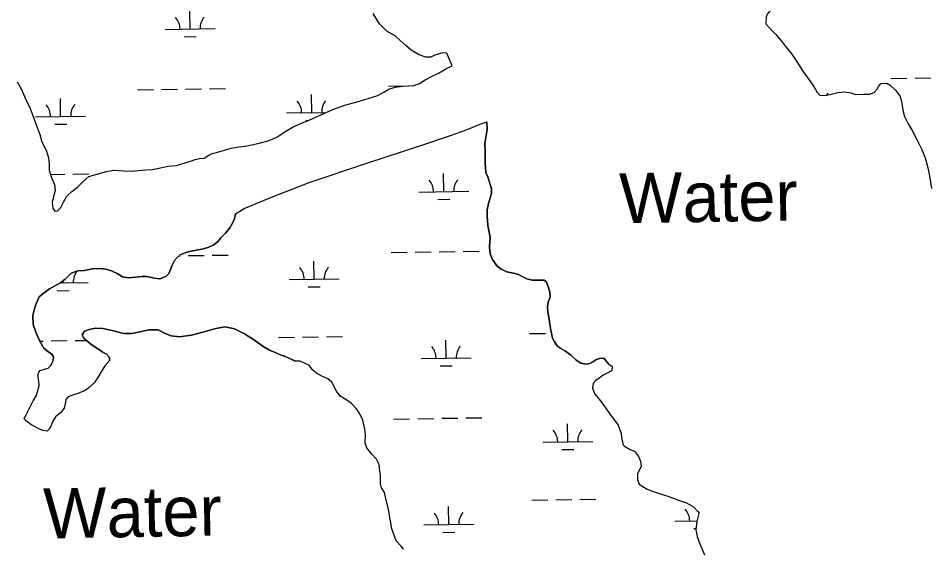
# Model space of a CAD drawing. Extents: x 3812694 to 3850888, y 319753 to 345638.
# Drawn here: x 3820130 to 3821954, y 335763 to 336823 of the extents above; entities that cross this region are included whole.
import ezdxf

# ---------------------------------------------------------------- set-up
doc = ezdxf.new("R2010")
doc.units = 0
for name, color, linetype in [('V-RIVR-IDEN', 7, 'Continuous'), ('V-TOPO-SHOR', 7, 'Continuous'), ('V-WETL-SWMP', 7, 'Continuous')]:
    doc.layers.add(name, color=color, linetype=linetype)

msp = doc.modelspace()

# ---------------------------------------------------------------- linework, layer by layer
at = {"layer": 'V-TOPO-SHOR'}
for points in [[(3822718.6, 337347.9), (3822729.1, 337350), (3822736.4, 337343), (3822761.6, 337270.6), (3822762.6, 337261.9), (3822761.8, 337259.2), (3822742.8, 337248.3), (3822605, 337198.7), (3822369.6, 337114.4), (3822324.5, 337103.7), (3822232.9, 337064.8), (3822065.7, 337003), (3821927.6, 336950.4), (3821828.7, 336915.3), (3821709.1, 336870.2), (3821667.3, 336856.5), (3821652.4, 336851.4), (3821643.1, 336846.5), (3821634.5, 336839.5), (3821630.6, 336835.4), (3821627.1, 336830.7), (3821625, 336824.9), (3821624.3, 336811.5)], [(3820997.4, 336727.2), (3820989.7, 336744.7), (3820986.6, 336752.6), (3820978.8, 336753.5), (3820962.2, 336748.6), (3820954.4, 336744.6), (3820944.8, 336745.1), (3820931.5, 336749.8), (3820915.5, 336758.7), (3820904.6, 336768.4), (3820892.3, 336779), (3820883.6, 336786.5), (3820866.8, 336796.7), (3820858.6, 336804.6), (3820851.7, 336811.5), (3820839.4, 336832.2)], [(3821624.3, 336811.5), (3821635.6, 336798.7), (3821644, 336789.8), (3821655.2, 336776.5), (3821663.8, 336766.2), (3821674.1, 336753.6), (3821683.1, 336740.9), (3821690.4, 336729.2), (3821698.5, 336716.6), (3821710.4, 336700.1), (3821719.9, 336686.3), (3821726.6, 336674.5)], [(3820501.6, 336542.9), (3820510.8, 336549.2), (3820517.5, 336552.1), (3820528.1, 336555.2), (3820541.9, 336559.3), (3820555.5, 336562.7), (3820571.1, 336565.5), (3820587.3, 336568), (3820599.4, 336570.2), (3820613.8, 336573.7), (3820629.4, 336578), (3820646.9, 336584.9), (3820664.7, 336597.1), (3820679.1, 336605.8), (3820696.1, 336613.3), (3820717.1, 336621.8), (3820740.9, 336632.3), (3820762, 336641.8), (3820784.5, 336649.8), (3820807.5, 336655.3), (3820846.4, 336667.3), (3820860.4, 336674.7), (3820870.6, 336680.6), (3820883.3, 336684.6), (3820897.9, 336686.7), (3820910.9, 336687.8), (3820920.3, 336688.4), (3820931.7, 336692.3), (3820943.5, 336699.5), (3820955.8, 336705.9), (3820970, 336713), (3820985.8, 336722), (3820997.4, 336727.2)], [(3820127.6, 336695.8), (3820136.5, 336680), (3820144, 336661.4), (3820153.4, 336642.1), (3820161.8, 336621), (3820167.2, 336606.2), (3820172.7, 336590.4), (3820176.5, 336577.4), (3820186, 336556.7), (3820190.4, 336543.5), (3820191.7, 336531.9), (3820191.6, 336518.2), (3820197, 336502.3), (3820202, 336490.7), (3820203.8, 336478.4), (3820200.9, 336468.8), (3820197.8, 336455.1), (3820199.1, 336443.2), (3820202.8, 336437.1), (3820208.5, 336437.8), (3820214.6, 336444.6), (3820219.9, 336454.8), (3820227, 336466.9), (3820236.9, 336476.5), (3820248.1, 336485.2), (3820259.2, 336496.1), (3820270.7, 336506.4), (3820284.6, 336510.7), (3820306, 336516.6), (3820320.9, 336518.9), (3820340.4, 336517.6), (3820358.1, 336516.8), (3820369.1, 336518.2), (3820384.6, 336519.5)], [(3821726.6, 336674.5), (3821732, 336669.1), (3821743.2, 336668.5), (3821755.1, 336671.2), (3821768, 336674), (3821781.7, 336675.6), (3821794.1, 336673.3), (3821803.7, 336670.5), (3821819.2, 336670.7), (3821832.4, 336670.7), (3821841.1, 336674), (3821846.8, 336680.8), (3821849.9, 336686.9), (3821854.3, 336692), (3821866, 336692.6), (3821872.7, 336688.8), (3821883.3, 336678.8), (3821892.4, 336667.3), (3821895.7, 336656.9), (3821897.8, 336639.1), (3821901.4, 336626.3), (3821908.7, 336611.7), (3821916.9, 336598), (3821926.3, 336580.5), (3821935.3, 336561.5), (3821942.5, 336543.7), (3821946.7, 336529.3), (3821950.1, 336514.5), (3821952.7, 336499.3), (3821955.3, 336482.4)], [(3820563.7, 336431.7), (3820573, 336437.3), (3820581.5, 336442.4), (3820593, 336447.4), (3820635.7, 336465.2), (3820711.2, 336494.6), (3820828.3, 336533.6), (3820936.5, 336569.2), (3820993.8, 336588.1), (3821016.8, 336596.3), (3821037.3, 336604.2), (3821047.9, 336608.9), (3821066.2, 336615.6)], [(3821309.4, 336132), (3821301.2, 336142.5), (3821299.3, 336143.4), (3821292, 336143), (3821288.8, 336142.1), (3821284.6, 336139.9), (3821278.6, 336135.8), (3821272.6, 336132.6), (3821264.8, 336131.3), (3821254.7, 336133.3), (3821244.2, 336140.2), (3821234.2, 336149.5), (3821223.8, 336157.4), (3821213.3, 336163.4), (3821206.4, 336169), (3821201, 336177.7), (3821197.8, 336183.7), (3821194.7, 336199.4), (3821192.6, 336211.3), (3821190.8, 336221.4), (3821188.6, 336235.7), (3821187.8, 336246.7), (3821189.3, 336255.4), (3821193, 336265.4), (3821192.6, 336275.5), (3821189.1, 336286.6), (3821185.5, 336295.3), (3821180.9, 336299), (3821167.6, 336299.6), (3821157.1, 336299.2), (3821146.5, 336302.1), (3821138.3, 336305.8), (3821130.1, 336310.5), (3821119.6, 336313.3), (3821106.3, 336315.7), (3821094.9, 336321.3), (3821086.7, 336327.8), (3821078, 336340.3), (3821073.1, 336351.8), (3821071.8, 336365.6), (3821072.9, 336385.3), (3821068.5, 336408.7), (3821066.9, 336428), (3821067, 336439.9), (3821069.8, 336452.3), (3821073.6, 336465.6), (3821076, 336473.8), (3821076, 336479.3), (3821076, 336481.6), (3821068.4, 336506), (3821064.8, 336514.3), (3821063.6, 336525.3), (3821063.2, 336533.5), (3821063.3, 336543.6), (3821062.9, 336556.9), (3821062.6, 336571.6), (3821064, 336580.3), (3821067.4, 336600), (3821066.2, 336615.6)], [(3820384.6, 336519.5), (3820398.4, 336520.7), (3820429.1, 336527.2), (3820445.9, 336528.7), (3820463.3, 336533.6), (3820469.3, 336536), (3820477.9, 336538.5), (3820483.5, 336540.3), (3820492.1, 336542.1), (3820501.6, 336542.9)], [(3820563.7, 336431.7), (3820561.7, 336421.8), (3820558.3, 336413), (3820552.7, 336404.1), (3820543.8, 336393.3), (3820535.2, 336384.4), (3820528.7, 336376.6), (3820521, 336369.7), (3820509.4, 336364.7), (3820496.4, 336361.3), (3820485.5, 336359.1), (3820474.8, 336357.3), (3820463.3, 336353.8), (3820453.5, 336349.7), (3820447.2, 336344.5), (3820442, 336338.8), (3820437.2, 336329.5), (3820433.8, 336320.8), (3820430.6, 336312.6), (3820424.6, 336306.3), (3820412.7, 336302.2), (3820401.4, 336303.1), (3820387.7, 336306.4), (3820376.6, 336306.8), (3820364.5, 336305.5), (3820349.9, 336304), (3820338.3, 336306.1), (3820327.2, 336312.9), (3820316.2, 336318.2), (3820307.6, 336320.7), (3820295.8, 336322.8), (3820277.5, 336321.7), (3820262.4, 336318.5), (3820248.6, 336318), (3820235.8, 336313.4), (3820229.5, 336307.5), (3820223.2, 336301.6), (3820214, 336293.7), (3820205.5, 336289.5), (3820192.3, 336282.1), (3820181.3, 336274.1), (3820171.6, 336265.8), (3820163.8, 336247.1), (3820158.6, 336228.6), (3820159.4, 336210.4), (3820164.8, 336195.7), (3820170.9, 336181.2), (3820178.9, 336166.7), (3820180.1, 336164.2), (3820188.9, 336156.9), (3820196.1, 336152.1), (3820200.2, 336146.4), (3820199.6, 336139.6)], [(3820312.5, 336139.2), (3820311.7, 336145.4), (3820306, 336151.1), (3820297.2, 336156.4), (3820294.4, 336158.8), (3820285.6, 336164.4), (3820274.6, 336171.3), (3820260.9, 336183.3), (3820257.6, 336190.1), (3820262, 336197.4), (3820271.5, 336201), (3820283.5, 336203.1), (3820299.1, 336202.6), (3820317.8, 336198.5), (3820341, 336192.8), (3820357.2, 336192.6), (3820376, 336196.5), (3820391.6, 336200), (3820409.1, 336199.9), (3820423.1, 336193), (3820435.6, 336188.3), (3820451.9, 336186), (3820476.1, 336189.2), (3820498.5, 336195.4), (3820524.6, 336202.6), (3820543.1, 336206.1), (3820562.3, 336202.2), (3820582.2, 336192.3), (3820601.7, 336179.5), (3820619.6, 336166.5), (3820631.8, 336159.7), (3820643.4, 336154.7), (3820655.3, 336149.7), (3820662.1, 336147.5), (3820663.6, 336146.5), (3820684.1, 336137.4)], [(3820312.5, 336139.2), (3820302.9, 336128.3), (3820295.4, 336116), (3820288.5, 336105.1), (3820281.6, 336094.2), (3820270.6, 336083.9), (3820263.8, 336078.5), (3820248.7, 336073.1), (3820238.4, 336069.7), (3820229.5, 336066.3), (3820224.7, 336060.8), (3820224, 336055.3), (3820221.2, 336043.7), (3820214.4, 336034.2), (3820204.1, 336026), (3820198.6, 336017.8), (3820193.1, 336002.7), (3820187.6, 335997.3), (3820178.7, 335998.7), (3820169.8, 336002.8), (3820154.8, 336011.1), (3820145.9, 336017.3), (3820141.8, 336022.7), (3820144.5, 336027.5), (3820159.7, 336058.3), (3820165.9, 336069.2), (3820168, 336076), (3820171.4, 336089), (3820170.8, 336097.2), (3820168.7, 336108.9), (3820170.8, 336115.7), (3820173.6, 336119.1), (3820182.5, 336121.2), (3820189.3, 336123.2), (3820194.8, 336128.6), (3820196.9, 336132.1), (3820199.6, 336139.6)], [(3820899.8, 335761.8), (3820895, 335767.9), (3820885.5, 335778.2), (3820876.7, 335802.2), (3820869.9, 335841.2), (3820864.5, 335863.1), (3820861.8, 335874.8), (3820855.7, 335884.4), (3820853.7, 335892.6), (3820853.7, 335909.7), (3820852.4, 335917.2), (3820851.1, 335930.9), (3820845.6, 335941.9), (3820836.1, 335952.2), (3820826.5, 335964.5), (3820823.1, 335974.1), (3820823.9, 335990.5), (3820822.5, 336001.5), (3820818.5, 336019.3), (3820812.4, 336032.3), (3820806.2, 336041.9), (3820796, 336052.9), (3820784.4, 336061.1), (3820773.5, 336067.3), (3820766, 336077.6), (3820756.5, 336095.4), (3820748.3, 336102.3), (3820738, 336107.1), (3820726.4, 336112.6), (3820717.5, 336120.9), (3820712.1, 336129.1), (3820693.6, 336137.4), (3820684.1, 336137.4)], [(3821309.4, 336132), (3821316.9, 336126.6), (3821316.9, 336124.5), (3821315.5, 336118.3), (3821307.3, 336113.6), (3821299.1, 336109.5), (3821290.9, 336103.4), (3821284.7, 336098.6), (3821279.2, 336092.5), (3821277.8, 336083.6), (3821282.6, 336071.2), (3821293.5, 336058.2), (3821311.9, 336032.8), (3821328.9, 336009.5), (3821335, 335993.1), (3821336.3, 335981.4), (3821339, 335970.5), (3821341.8, 335967.7), (3821352.7, 335960.9), (3821361.6, 335957.4), (3821369.8, 335947.1), (3821373.8, 335937.5), (3821375.2, 335927.9), (3821373.1, 335923.2), (3821367.6, 335912.9), (3821367.6, 335901.3), (3821371, 335891.7), (3821387.3, 335881.4), (3821405.1, 335875.2), (3821430.4, 335866.9), (3821449.5, 335860), (3821465.3, 335854.5), (3821479.6, 335846.2), (3821488.5, 335837.3), (3821491.2, 335833.9), (3821490.5, 335833.2), (3821486.4, 335816.8), (3821484.3, 335800.3), (3821487, 335787.3), (3821492.4, 335772.3), (3821501.9, 335750.3)]]:
    msp.add_lwpolyline(points, dxfattribs=at)
at = {"layer": 'V-WETL-SWMP'}
for p, q in [((3820473.3, 336801.2), (3820472.7, 336837.2)), ((3820423.3, 336800.4), (3820523.3, 336801.9)), ((3820461.5, 336785.6), (3820485.5, 336785.9)), ((3820870.1, 336687.1), (3820902.1, 336687.6)), ((3821873.8, 336702.3), (3821905.8, 336702.8)), ((3821921.8, 336703), (3821953.8, 336703.5)), ((3820368.3, 336679.5), (3820400.3, 336680)), ((3820416.3, 336680.2), (3820448.3, 336680.7)), ((3820464.2, 336680.9), (3820496.2, 336681.4)), ((3820512.2, 336681.7), (3820544.2, 336682.2)), ((3820716.3, 336634), (3820715.8, 336670)), ((3820214.5, 336626.4), (3820213.9, 336662.4)), ((3820666.3, 336633.3), (3820745.6, 336634.5)), ((3820164.5, 336625.7), (3820264.4, 336627.2)), ((3820704.5, 336618.4), (3820708.8, 336618.5)), ((3820202.7, 336610.8), (3820226.7, 336611.2)), ((3820194.1, 336510.7), (3820222.8, 336511.1)), ((3820238.8, 336511.3), (3820270.8, 336511.8)), ((3820980.2, 336476.1), (3820979.6, 336512.1)), ((3820930.2, 336475.4), (3821030.2, 336476.9)), ((3820968.4, 336460.5), (3820992.4, 336460.9)), ((3820451.6, 336348), (3820453.3, 336348.1)), ((3820469.3, 336348.3), (3820501.3, 336348.8)), ((3820517.3, 336349), (3820549.3, 336349.5)), ((3820875.1, 336354.4), (3820907.1, 336354.9)), ((3820923.1, 336355.2), (3820955.1, 336355.7)), ((3820971.1, 336355.9), (3821003.1, 336356.4)), ((3821019.1, 336356.6), (3821051.1, 336357.1)), ((3820721.3, 336301.4), (3820720.8, 336337.4)), ((3820213.9, 336293.7), (3820269.5, 336294.5)), ((3820219.5, 336293.8), (3820219.4, 336298.4)), ((3820671.3, 336300.6), (3820771.3, 336302.1)), ((3820709.6, 336285.8), (3820733.6, 336286.1)), ((3820207.7, 336278.2), (3820231.7, 336278.5)), ((3820172.8, 336177.6), (3820179.8, 336177.7)), ((3820195.8, 336178), (3820227.8, 336178.5)), ((3820243.8, 336178.7), (3820265.8, 336179)), ((3820649.7, 336184.8), (3820681.7, 336185.3)), ((3820697.7, 336185.6), (3820729.7, 336186.1)), ((3820745.7, 336186.3), (3820777.7, 336186.8)), ((3820985.2, 336143.5), (3820984.6, 336179.5)), ((3821151.5, 336192.4), (3821183.5, 336192.9)), ((3820935.2, 336142.7), (3821035.2, 336144.2)), ((3820973.4, 336127.9), (3820997.4, 336128.2)), ((3820880.2, 336021.8), (3820912.2, 336022.3)), ((3820928.2, 336022.5), (3820960.2, 336023)), ((3820976.2, 336023.3), (3821008.2, 336023.7)), ((3821024.2, 336024), (3821056.2, 336024.5)), ((3821228.2, 335976.3), (3821227.7, 336012.3)), ((3821178.2, 335975.6), (3821278.2, 335977.1)), ((3821216.5, 335960.7), (3821240.5, 335961.1)), ((3821156.6, 335859.8), (3821188.6, 335860.3)), ((3821204.6, 335860.5), (3821236.6, 335861)), ((3821252.6, 335861.2), (3821284.6, 335861.7)), ((3820990.2, 335810.8), (3820989.7, 335846.8)), ((3821442.1, 335817.7), (3821486.8, 335818.4)), ((3820940.2, 335810.1), (3821040.2, 335811.6)), ((3820978.5, 335795.2), (3821002.5, 335795.6)), ((3821480.3, 335802.8), (3821484.6, 335802.9))]:
    msp.add_line(p, q, dxfattribs=at)
for points in [[(3820127.6, 336695.8), (3820136.5, 336680), (3820144, 336661.4), (3820153.4, 336642.1), (3820161.8, 336621), (3820167.2, 336606.2), (3820172.7, 336590.4), (3820176.5, 336577.4), (3820186, 336556.7), (3820190.4, 336543.5), (3820191.7, 336531.9), (3820191.6, 336518.2), (3820197, 336502.3), (3820202, 336490.7), (3820203.8, 336478.4), (3820200.9, 336468.8), (3820197.8, 336455.1), (3820199.1, 336443.2), (3820202.8, 336437.1), (3820208.5, 336437.8), (3820214.6, 336444.6), (3820219.9, 336454.8), (3820227, 336466.9), (3820236.9, 336476.5), (3820248.1, 336485.2), (3820259.2, 336496.1), (3820270.7, 336506.4), (3820284.6, 336510.7), (3820306, 336516.6), (3820320.9, 336518.9), (3820340.4, 336517.6), (3820358.1, 336516.8), (3820369.1, 336518.2), (3820384.6, 336519.5), (3820398.4, 336520.7), (3820429.1, 336527.2), (3820445.9, 336528.7), (3820463.3, 336533.6), (3820469.3, 336536), (3820477.9, 336538.5), (3820483.5, 336540.3), (3820492.1, 336542.1), (3820501.6, 336542.9), (3820510.8, 336549.2), (3820517.5, 336552.1), (3820528.1, 336555.2), (3820541.9, 336559.3), (3820555.5, 336562.7), (3820571.1, 336565.5), (3820587.3, 336568), (3820599.4, 336570.2), (3820613.8, 336573.7), (3820629.4, 336578), (3820646.9, 336584.9), (3820664.7, 336597.1), (3820679.1, 336605.8), (3820696.1, 336613.3), (3820717.1, 336621.8), (3820740.9, 336632.3), (3820762, 336641.8), (3820784.5, 336649.8), (3820807.5, 336655.3), (3820846.4, 336667.3), (3820860.4, 336674.7), (3820870.6, 336680.6), (3820883.3, 336684.6), (3820897.9, 336686.7), (3820910.9, 336687.8), (3820920.3, 336688.4), (3820931.7, 336692.3), (3820943.5, 336699.5), (3820955.8, 336705.9), (3820970, 336713), (3820985.8, 336722), (3820997.4, 336727.2), (3820989.7, 336744.7), (3820986.6, 336752.6), (3820978.8, 336753.5), (3820962.2, 336748.6), (3820954.4, 336744.6), (3820944.8, 336745.1), (3820931.5, 336749.8), (3820915.5, 336758.7), (3820904.6, 336768.4), (3820892.3, 336779), (3820883.6, 336786.5), (3820866.8, 336796.7), (3820858.6, 336804.6), (3820851.7, 336811.5), (3820839.4, 336832.2)], [(3821625, 336824.9), (3821624.3, 336811.5), (3821635.6, 336798.7), (3821644, 336789.8), (3821655.2, 336776.5), (3821663.8, 336766.2), (3821674.1, 336753.6), (3821683.1, 336740.9), (3821690.4, 336729.2), (3821698.5, 336716.6), (3821710.4, 336700.1), (3821719.9, 336686.3), (3821726.6, 336674.5), (3821732, 336669.1), (3821743.2, 336668.5), (3821755.1, 336671.2), (3821768, 336674), (3821781.7, 336675.6), (3821794.1, 336673.3), (3821803.7, 336670.5), (3821819.3, 336670.7), (3821832.4, 336670.7), (3821841.1, 336674), (3821846.8, 336680.8), (3821849.9, 336686.9), (3821854.3, 336692), (3821866, 336692.6), (3821872.7, 336688.8), (3821883.3, 336678.8), (3821892.4, 336667.3), (3821895.7, 336656.9), (3821897.8, 336639.1), (3821901.4, 336626.3), (3821908.7, 336611.7), (3821916.9, 336598), (3821926.3, 336580.5), (3821935.3, 336561.5), (3821942.5, 336543.7), (3821946.7, 336529.3), (3821950.1, 336514.5), (3821952.7, 336499.3), (3821955.3, 336482.4)], [(3820376.6, 336306.8), (3820387.7, 336306.4), (3820401.4, 336303.1), (3820412.7, 336302.2), (3820424.6, 336306.3), (3820430.6, 336312.6), (3820433.8, 336320.8), (3820437.2, 336329.5), (3820442, 336338.8), (3820447.2, 336344.5), (3820453.5, 336349.7), (3820463.3, 336353.8), (3820474.8, 336357.3), (3820485.5, 336359.1), (3820496.4, 336361.3), (3820509.4, 336364.7), (3820521, 336369.7), (3820528.7, 336376.6), (3820535.2, 336384.4), (3820543.8, 336393.3), (3820552.7, 336404.1), (3820558.3, 336413), (3820561.7, 336421.8), (3820563.7, 336431.7), (3820573, 336437.3), (3820581.5, 336442.4), (3820593, 336447.4), (3820635.7, 336465.2), (3820711.2, 336494.6), (3820828.3, 336533.6), (3820936.5, 336569.2), (3820993.8, 336588.1), (3821016.8, 336596.3), (3821037.3, 336604.2), (3821047.9, 336608.9), (3821066.2, 336615.6), (3821067.4, 336600), (3821064, 336580.3), (3821062.6, 336571.6), (3821062.9, 336556.9), (3821063.3, 336543.6), (3821063.2, 336533.5), (3821063.6, 336525.3), (3821064.8, 336514.3), (3821068.4, 336506), (3821076, 336481.6), (3821076, 336479.3), (3821076, 336473.8), (3821073.6, 336465.6), (3821069.8, 336452.3), (3821067, 336439.9), (3821066.9, 336428), (3821068.5, 336408.7), (3821072.9, 336385.3), (3821071.8, 336365.6), (3821073.1, 336351.8), (3821078, 336340.3), (3821086.7, 336327.8), (3821094.9, 336321.3), (3821106.3, 336315.7), (3821119.6, 336313.3), (3821130.1, 336310.5), (3821138.3, 336305.8), (3821146.5, 336302.1), (3821157.1, 336299.2), (3821167.6, 336299.6), (3821180.9, 336299), (3821185.5, 336295.3), (3821189.1, 336286.6), (3821192.6, 336275.5), (3821193, 336265.4), (3821189.3, 336255.4), (3821187.8, 336246.7), (3821188.6, 336235.7), (3821190.8, 336221.4), (3821192.6, 336211.3), (3821194.7, 336199.4), (3821197.8, 336183.7), (3821201, 336177.7), (3821206.4, 336169), (3821213.3, 336163.4), (3821223.8, 336157.4), (3821234.2, 336149.5), (3821244.2, 336140.2), (3821254.7, 336133.3), (3821264.8, 336131.3), (3821272.6, 336132.6), (3821278.6, 336135.8), (3821284.6, 336139.9), (3821288.8, 336142.1), (3821292, 336143), (3821299.3, 336143.4), (3821301.2, 336142.5), (3821309.4, 336132), (3821316.9, 336126.6), (3821316.9, 336124.5), (3821315.5, 336118.3), (3821307.3, 336113.6), (3821299.1, 336109.5), (3821290.9, 336103.4), (3821284.7, 336098.6)], [(3820684.1, 336137.4), (3820663.6, 336146.5), (3820662.1, 336147.5), (3820655.3, 336149.7), (3820643.4, 336154.7), (3820631.8, 336159.7), (3820619.6, 336166.5), (3820601.7, 336179.5), (3820582.2, 336192.3), (3820562.3, 336202.2), (3820543.1, 336206.1), (3820524.6, 336202.6), (3820498.5, 336195.4), (3820476.1, 336189.2), (3820451.9, 336186), (3820435.6, 336188.3), (3820423.1, 336193), (3820409.1, 336199.9), (3820391.6, 336200), (3820376, 336196.5), (3820357.2, 336192.6), (3820341, 336192.8), (3820317.8, 336198.5), (3820299.1, 336202.6), (3820283.5, 336203.1), (3820271.5, 336201), (3820262, 336197.4), (3820257.6, 336190.1), (3820260.9, 336183.3), (3820274.6, 336171.3), (3820285.6, 336164.4), (3820294.4, 336158.8), (3820297.2, 336156.4), (3820306, 336151.1), (3820311.7, 336145.4), (3820312.5, 336139.2), (3820302.9, 336128.3), (3820295.4, 336116), (3820288.5, 336105.1), (3820281.6, 336094.2), (3820270.6, 336083.9), (3820263.8, 336078.5), (3820248.7, 336073.1), (3820238.4, 336069.7), (3820229.5, 336066.3), (3820224.7, 336060.8), (3820224, 336055.3), (3820221.2, 336043.7), (3820214.4, 336034.2), (3820204.1, 336026), (3820198.6, 336017.8), (3820193.1, 336002.7), (3820187.6, 335997.3), (3820178.7, 335998.7), (3820169.8, 336002.8), (3820154.8, 336011.1), (3820145.9, 336017.3), (3820141.8, 336022.7), (3820144.5, 336027.5), (3820159.7, 336058.3), (3820165.9, 336069.2), (3820168, 336076), (3820171.4, 336089), (3820170.8, 336097.2), (3820168.7, 336108.9), (3820170.8, 336115.7), (3820173.6, 336119.1), (3820182.5, 336121.2), (3820189.3, 336123.2), (3820194.8, 336128.6), (3820196.9, 336132.1), (3820199.6, 336139.6), (3820200.2, 336146.4), (3820196.1, 336152.1), (3820188.9, 336156.9), (3820180.1, 336164.2), (3820178.9, 336166.7), (3820170.9, 336181.2), (3820164.8, 336195.7), (3820159.4, 336210.4), (3820158.6, 336228.6), (3820163.8, 336247.1), (3820171.6, 336265.8), (3820181.3, 336274.1), (3820192.3, 336282.1), (3820205.5, 336289.5), (3820214, 336293.7), (3820223.2, 336301.6), (3820229.5, 336307.5), (3820235.8, 336313.4), (3820248.6, 336318), (3820262.4, 336318.5), (3820277.5, 336321.7), (3820295.8, 336322.8), (3820307.6, 336320.7), (3820316.2, 336318.2), (3820327.2, 336312.9), (3820338.3, 336306.1), (3820349.9, 336304), (3820364.5, 336305.5), (3820376.6, 336306.8)], [(3820899.8, 335761.8), (3820895, 335767.9), (3820885.5, 335778.2), (3820876.7, 335802.2), (3820869.9, 335841.2), (3820864.5, 335863.1), (3820861.8, 335874.8), (3820855.7, 335884.4), (3820853.7, 335892.6), (3820853.7, 335909.7), (3820852.4, 335917.2), (3820851.1, 335930.9), (3820845.6, 335941.9), (3820836.1, 335952.2), (3820826.5, 335964.5), (3820823.1, 335974.1), (3820823.9, 335990.5), (3820822.5, 336001.5), (3820818.5, 336019.3), (3820812.4, 336032.3), (3820806.2, 336041.9), (3820796, 336052.9), (3820784.4, 336061.1), (3820773.5, 336067.3), (3820766, 336077.6), (3820756.5, 336095.4), (3820748.3, 336102.3), (3820738, 336107.1), (3820726.4, 336112.6), (3820717.5, 336120.9), (3820712.1, 336129.1), (3820693.6, 336137.4), (3820684.1, 336137.4)], [(3821284.7, 336098.6), (3821279.2, 336092.5), (3821277.8, 336083.6), (3821282.6, 336071.2), (3821293.5, 336058.2), (3821311.9, 336032.8), (3821328.9, 336009.5), (3821335, 335993.1), (3821336.3, 335981.4), (3821339, 335970.5), (3821341.8, 335967.7), (3821352.7, 335960.9), (3821361.6, 335957.4), (3821369.8, 335947.1), (3821373.8, 335937.5), (3821375.2, 335927.9), (3821373.1, 335923.2), (3821367.6, 335912.9), (3821367.6, 335901.3), (3821371, 335891.7), (3821387.3, 335881.4), (3821405.1, 335875.2), (3821430.4, 335866.9), (3821449.5, 335860), (3821465.3, 335854.5), (3821479.6, 335846.2), (3821488.5, 335837.3), (3821491.2, 335833.9), (3821490.5, 335833.2), (3821486.4, 335816.8), (3821484.3, 335800.3), (3821487, 335787.3), (3821492.4, 335772.3), (3821501.9, 335750.3)]]:
    msp.add_lwpolyline(points, dxfattribs=at)
for centre, start, end in [((3820418, 336800.8), 0.0949, 41.6385), ((3820528.5, 336802.5), 140.0949, 181.6385), ((3821775.2, 336650.5), 140.0949, 148.3222), ((3820661.1, 336633.6), 0.0949, 41.6385), ((3820771.5, 336635.3), 140.0949, 181.6385), ((3820159.2, 336626.1), 0.0949, 41.6385), ((3820269.7, 336627.7), 140.0949, 181.6385), ((3820924.9, 336475.8), 0.0949, 41.6385), ((3821035.4, 336477.4), 140.0949, 181.6385), ((3820666.1, 336301), 0.0949, 41.6385), ((3820776.6, 336302.7), 140.0949, 181.6385), ((3820274.7, 336295.1), 140.3152, 181.6385), ((3820929.9, 336143.1), 0.0949, 41.6385), ((3821040.4, 336144.8), 140.0949, 181.6385), ((3821173, 335976), 0.0949, 41.6385), ((3821283.4, 335977.6), 140.0949, 181.6385), ((3820935, 335810.5), 0.0949, 41.6385), ((3821045.5, 335812.2), 140.0949, 181.6385), ((3821436.8, 335818.1), 0.0949, 41.6385)]:
    msp.add_arc(centre, 35.2, start, end, dxfattribs=at)

# ---------------------------------------------------------------- texts
at = {"layer": 'V-RIVR-IDEN'}
for p in [(3821332.1, 336412.7), (3820180.8, 335783)]:
    msp.add_text('Water', height=100, rotation=0.975, dxfattribs=at).set_placement(p)

doc.saveas('drawing.dxf')
